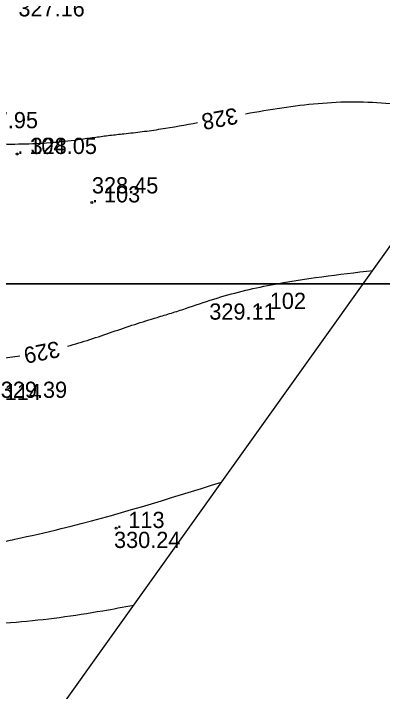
# Model space of a CAD drawing. Extents: x 4632591 to 4653165, y 5351032 to 5369868.
# Drawn here: x 4644728.1 to 4644762.2, y 5358462.3 to 5358525 of the extents above; entities that cross this region are included whole.
import ezdxf

# ---------------------------------------------------------------- set-up
doc = ezdxf.new("R2010")
doc.units = 0
for name, color, linetype in [('Warstwa 40', 7, 'Continuous'), ('Warstwa 60', 7, 'Continuous'), ('Warstwa 62', 7, 'Continuous'), ('WUKPS_403', 7, 'Continuous'), ('WWRPH_811', 7, 'Continuous')]:
    doc.layers.add(name, color=color, linetype=linetype)

msp = doc.modelspace()

# ---------------------------------------------------------------- linework, layer by layer
at = {"layer": 'Warstwa 40'}
msp.add_lwpolyline([(4644810.829869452, 5358555.0318941), (4644734.3245207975, 5358627.5855483), (4644688.903956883, 5358576.341480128), (4644696.208771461, 5358541.053777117), (4644665.649831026, 5358513.078865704), (4644675.210413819, 5358482.874703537), (4644634.264162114, 5358446.154900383), (4644624.659923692, 5358448.078175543), (4644610.340877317, 5358444.40646842), (4644593.08287162, 5358445.769308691), (4644584.820738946, 5358446.421757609), (4644558.950406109, 5358331.354730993), (4644690.288366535, 5358293.195203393), (4644705.733104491, 5358386.519320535), (4644692.287170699, 5358404.571880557), (4644776.589601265, 5358522.671629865)], close=True, dxfattribs=at)
at = {"layer": 'Warstwa 60'}
for points in [[(4644000, 5358500), (4644000, 5359000), (4644800, 5359000), (4644800, 5358500)], [(4644000, 5358000), (4644000, 5358500), (4644800, 5358500), (4644800, 5358000)]]:
    msp.add_lwpolyline(points, close=True, dxfattribs=at)
at = {"layer": 'WUKPS_403'}
for centre in [(4644728.42, 5358512.0200000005), (4644735.33, 5358507.54), (4644750.66, 5358497.68), (4644737.583005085, 5358477.405736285)]:
    msp.add_circle(centre, 0.09, dxfattribs=at)
at = {"layer": 'WWRPH_811'}
msp.add_line((4644708.959016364, 5358490.691669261), (4644728.672319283, 5358493.354334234), dxfattribs=at)
for points in [[(4644771.62738981, 5358515.720039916), (4644762.939897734, 5358516.659724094), (4644759.588817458, 5358516.828865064), (4644756.238759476, 5358516.6693922), (4644752.889382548, 5358516.268575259), (4644749.54034543, 5358515.7136839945)], [(4644745.102116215, 5358514.8899878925), (4644741.694179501, 5358514.305138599), (4644739.989922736, 5358514.060397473), (4644738.285413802, 5358513.86276396), (4644736.9862650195, 5358513.716260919), (4644735.686767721, 5358513.546578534), (4644733.086087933, 5358513.199768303), (4644727.873510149, 5358512.911014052), (4644721.7485651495, 5358513.1801971)], [(4644733.06005873, 5358494.225019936), (4644735.14446674, 5358494.857146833), (4644737.21562525, 5358495.552300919), (4644739.285814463, 5358496.2523608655), (4644741.36731458, 5358496.899205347), (4644742.677796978, 5358497.296708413), (4644743.982334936, 5358497.722346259), (4644746.588106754, 5358498.589594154), (4644751.888138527, 5358499.90895382), (4644761.294019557, 5358501.243963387)], [(4644721.443949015, 5358475.444619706), (4644724.501238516, 5358475.728007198), (4644726.396855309, 5358475.993655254), (4644728.214544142, 5358476.369819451), (4644732.475764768, 5358477.349430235), (4644747.3131549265, 5358481.658091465)], [(4644717.774119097, 5358468.344594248), (4644720.263041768, 5358468.324274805), (4644724.2850643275, 5358468.433265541), (4644728.315198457, 5358468.702110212), (4644732.334535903, 5358469.1400206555), (4644736.324168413, 5358469.7562087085), (4644739.181376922, 5358470.266237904)]]:
    msp.add_spline(points, degree=3, dxfattribs=at)

# ---------------------------------------------------------------- texts
at = {"layer": 'Warstwa 62'}
for s, p in [('. 104', (4644728.42, 5358512.0200000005)), ('. 103', (4644735.33, 5358507.54)), ('. 102', (4644750.66, 5358497.68)), ('. 114', (4644726.15, 5358489.24)), ('. 113', (4644737.583005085, 5358477.405736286))]:
    msp.add_text(s, height=1.5, dxfattribs=at).set_placement(p)
at = {"layer": 'WUKPS_403'}
for s, p in [('327.16', (4644728.531561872, 5358524.751442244)), ('327.95', (4644724.20590097, 5358514.402099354)), ('328.05', (4644729.655280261, 5358512.0200000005)), ('328.45', (4644735.33, 5358508.3692835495)), ('329.11', (4644746.182890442, 5358496.688924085)), ('329.39', (4644726.899149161, 5358489.450780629)), ('330.24', (4644737.37458965, 5358475.559368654))]:
    msp.add_text(s, height=1.5, dxfattribs=at).set_placement(p)
at = {"layer": 'WWRPH_811'}
for s, rotation, p in [('328', 190.6196342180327, (4644748.66389605, 5358516.31861661)), ('329', 191.30615227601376, (4644732.201027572, 5358494.728889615))]:
    msp.add_text(s, height=1.5, rotation=rotation, dxfattribs=at).set_placement(p)

doc.saveas('drawing.dxf')
